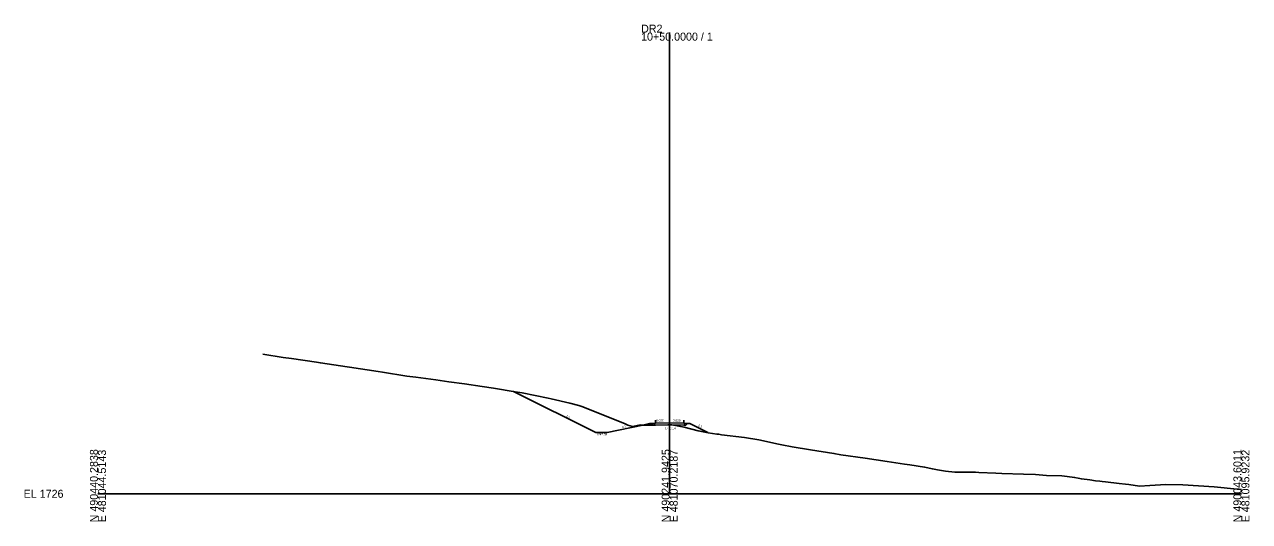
# Model space of a CAD drawing. Extents: x -26 to 403, y -10 to 2576.
# Drawn here: x -25.7 to 402.8, y 490.3 to 664.1 of the extents above; entities that cross this region are included whole.
import ezdxf

# ---------------------------------------------------------------- set-up
doc = ezdxf.new("R2010")
doc.units = 0
for name, color, linetype in [('Exist Cross Section Cell', 7, 'Continuous'), ('Exist XS Center Line Elevation Label', 7, 'Continuous'), ('Exist XS Ground Line', 7, 'Continuous'), ('Prop Road Sect_ Boring - Header (ID Tx)', 7, 'Continuous'), ('Prop XS Ditch Slope Text', 7, 'Continuous'), ('Prop XS Ditch Standard Text', 7, 'Continuous'), ('Prop XS Dump Level', 7, 'Continuous'), ('Prop XS Earthwork Shape', 7, 'Continuous'), ('Prop XS EOT Tick Mark', 7, 'Continuous'), ('Prop XS Finish Grade', 7, 'Continuous'), ('Prop XS Finish Grade Earthwork', 7, 'Continuous'), ('Prop XS Finish Grade Pavement', 7, 'Continuous'), ('Prop XS Pvmt Edge Slope', 7, 'Continuous'), ('Prop XS SE Text', 7, 'Continuous'), ('Prop XS Side Slope Text', 7, 'Continuous'), ('Prop XS Subgrade Earthwork', 7, 'Continuous')]:
    doc.layers.add(name, color=color, linetype=linetype)

msp = doc.modelspace()

# ---------------------------------------------------------------- linework, layer by layer
at = {"layer": 'Exist Cross Section Cell'}
for p, q in [((200, 500), (200, 661.3)), ((0, 500), (200, 500)), ((200, 500), (400, 500))]:
    msp.add_line(p, q, dxfattribs=at)
at = {"layer": 'Exist XS Ground Line'}
msp.add_lwpolyline([(57.65, 548.84), (64.83, 547.71), (67.74, 547.3), (76.42, 546.02), (77.82, 545.78), (87.24, 544.44), (88.01, 544.33), (97.99, 542.75), (99.6, 542.51), (108.08, 541.19), (111.18, 540.75), (118.16, 539.88), (122.77, 539.21), (128.25, 538.41), (134.36, 537.52), (138.34, 536.96), (145.94, 535.7), (148.42, 535.27), (157.53, 533.46), (158.51, 533.27), (165.06, 531.64), (168.19, 530.85), (168.88, 530.65), (169.58, 530.38), (184.48, 524.44), (185.31, 523.98), (187, 523.56), (189.19, 523.95), (189.69, 524.07), (190.34, 524.05), (192.44, 524), (199.38, 524.14), (200, 524.14), (200.41, 524.14), (200.71, 524.1), (205.08, 523.28), (210.02, 522), (213.46, 521.36), (216.49, 520.88), (217.23, 520.8), (218.14, 520.63), (226.19, 519.64), (231.19, 518.83), (238.11, 517.37), (239.19, 517.15), (242.88, 516.46), (249.28, 515.32), (257.47, 514.1), (259.91, 513.67), (268.4, 512.49), (276.12, 511.29), (282.15, 510.36), (283.96, 510.13), (289.18, 509.36), (291.93, 508.72), (293.66, 508.39), (296.49, 507.97), (299.79, 507.54), (306.98, 507.52), (308.17, 507.49), (314.14, 507.17), (316.22, 507.11), (323.83, 506.91), (327.99, 506.74), (331.84, 506.4), (337.22, 506.3), (339, 506.05), (341.65, 505.71), (342.93, 505.42), (344.04, 505.22), (346.93, 504.83), (348.97, 504.57), (350.51, 504.44), (351.25, 504.35), (352.43, 504.17), (357.28, 503.62), (359.47, 503.34), (360.64, 503.21), (364.41, 502.72), (367.97, 502.95), (373.59, 503.28), (379.54, 503.14), (390.48, 502.48), (398.53, 501.63), (400, 501.46)], dxfattribs=at)
at = {"layer": 'Prop Road Sect_ Boring - Header (ID Tx)'}
for points in [[(195, 524.71), (194.32, 524.03), (193.74, 524.61)], [(205.68, 524.03), (206.26, 524.61), (205, 524.71)]]:
    msp.add_lwpolyline(points, close=True, dxfattribs=at)
at = {"layer": 'Prop XS Dump Level'}
for p, q in [((200, 524.81), (195, 524.71)), ((205, 524.71), (200, 524.81))]:
    msp.add_line(p, q, dxfattribs=at)
at = {"layer": 'Prop XS Earthwork Shape'}
for p, q in [((145.34, 535.8), (174.15, 521.39)), ((157.53, 533.46), (148.42, 535.27)), ((158.51, 533.27), (157.53, 533.46)), ((165.06, 531.64), (158.51, 533.27)), ((178.15, 521.39), (190.6, 524.04)), ((189.19, 523.95), (187, 523.56)), ((190.6, 524.04), (190.34, 524.05)), ((193, 524.55), (190.6, 524.04)), ((190.6, 524.04), (192.44, 524)), ((192.44, 524), (194.31, 524.04)), ((193.74, 524.61), (193, 524.55)), ((194.31, 524.04), (193.74, 524.61)), ((199.38, 524.14), (195, 524.05)), ((195, 524.05), (199.38, 524.13)), ((205, 524.05), (200.43, 524.14)), ((200.43, 524.14), (200.71, 524.1)), ((200.71, 524.1), (205.08, 523.28)), ((205.68, 524.03), (205, 524.05)), ((205.08, 523.28), (210.02, 522)), ((206.26, 524.61), (205.68, 524.03)), ((207, 524.55), (206.26, 524.61)), ((213.35, 521.38), (207, 524.55)), ((174.15, 521.39), (178.15, 521.39)), ((210.02, 522), (213.35, 521.38))]:
    msp.add_line(p, q, dxfattribs=at)
for points in [[(148.42, 535.27), (145.94, 535.7), (145.34, 535.8)], [(168.88, 530.65), (168.19, 530.85), (165.06, 531.64)], [(187, 523.56), (185.31, 523.98), (184.48, 524.44), (169.58, 530.38), (168.88, 530.65)], [(190.34, 524.05), (189.69, 524.07), (189.19, 523.95)], [(190.6, 524.04), (190.6, 524.04)], [(195, 524.05), (195, 524.05)], [(199.38, 524.13), (199.38, 524.14)]]:
    msp.add_lwpolyline(points, dxfattribs=at)
msp.add_lwpolyline([(199.7, 524.14), (200, 524.15), (200.26, 524.14), (200.02, 524.14), (199.98, 524.14), (199.95, 524.14), (199.91, 524.14), (199.87, 524.14), (199.74, 524.14)], close=True, dxfattribs=at)
at = {"layer": 'Prop XS EOT Tick Mark'}
for p, q in [((195, 524.71), (195, 525.71)), ((205, 524.71), (205, 525.71))]:
    msp.add_line(p, q, dxfattribs=at)
at = {"layer": 'Prop XS Finish Grade'}
for p, q in [((195, 524.71), (193.74, 524.61)), ((205, 524.71), (206.26, 524.61))]:
    msp.add_line(p, q, dxfattribs=at)
at = {"layer": 'Prop XS Finish Grade Earthwork'}
for p, q in [((145.34, 535.8), (174.15, 521.39)), ((178.15, 521.39), (190.6, 524.04)), ((193, 524.55), (190.6, 524.04)), ((193.74, 524.61), (193, 524.55)), ((206.26, 524.61), (207, 524.55)), ((207, 524.55), (213.35, 521.38)), ((174.15, 521.39), (178.15, 521.39))]:
    msp.add_line(p, q, dxfattribs=at)
at = {"layer": 'Prop XS Finish Grade Pavement'}
for p, q in [((195, 524.71), (200, 524.81)), ((200, 524.81), (205, 524.71))]:
    msp.add_line(p, q, dxfattribs=at)
at = {"layer": 'Prop XS Pvmt Edge Slope'}
for p, q in [((195, 524.71), (194.32, 524.03)), ((205, 524.71), (205.68, 524.03))]:
    msp.add_line(p, q, dxfattribs=at)
at = {"layer": 'Prop XS Subgrade Earthwork'}
for p, q in [((194.32, 524.03), (193.74, 524.61)), ((195, 524.05), (194.32, 524.03)), ((200, 524.15), (195, 524.05)), ((205, 524.05), (200, 524.15)), ((205, 524.05), (205.68, 524.03)), ((205.68, 524.03), (206.26, 524.61))]:
    msp.add_line(p, q, dxfattribs=at)

# ---------------------------------------------------------------- texts
at = {"layer": 'Exist Cross Section Cell'}
for s, p in [('10+50.0000 / 1', (190, 658.5)), ('DR2', (190, 661.3)), ('EL 1726', (-26, 498.6))]:
    msp.add_text(s, height=2.8, dxfattribs=at).set_placement(p)
for s, p in [('N 490440.2838', (0, 490)), ('E 481044.5143', (2.8, 490)), ('N 490241.9425', (200, 490)), ('E 481070.2187', (202.8, 490)), ('N 490043.6011', (400, 490)), ('E 481095.9232', (402.8, 490))]:
    msp.add_text(s, height=2.8, rotation=90, dxfattribs=at).set_placement(p)
at = {"layer": 'Exist XS Center Line Elevation Label'}
msp.add_text('1750.14', height=0.75, dxfattribs=at).set_placement((198.38, 522.54))
at = {"layer": 'Prop XS Ditch Slope Text'}
msp.add_text('4:1', height=0.75, rotation=14.0362, dxfattribs=at).set_placement((183.41, 522.94))
at = {"layer": 'Prop XS Ditch Standard Text'}
msp.add_text('1747.39', height=0.75, dxfattribs=at).set_placement((174.37, 520.4))
at = {"layer": 'Prop XS Dump Level'}
for p in [(193, 524.51), (207, 524.51)]:
    msp.add_text('Case1', height=0.04, dxfattribs=at).set_placement(p)
at = {"layer": 'Prop XS SE Text'}
for rotation, p in [(1.1458, (195.29, 525.24)), (358.8542, (201.18, 525.29))]:
    msp.add_text('0.020', height=0.75, rotation=rotation, dxfattribs=at).set_placement(p)
at = {"layer": 'Prop XS Side Slope Text'}
for rotation, p in [(334.1739, (163.73, 526.95)), (333.4349, (209.86, 523.68))]:
    msp.add_text('2:1', height=0.75, rotation=rotation, dxfattribs=at).set_placement(p)

doc.saveas('drawing.dxf')
